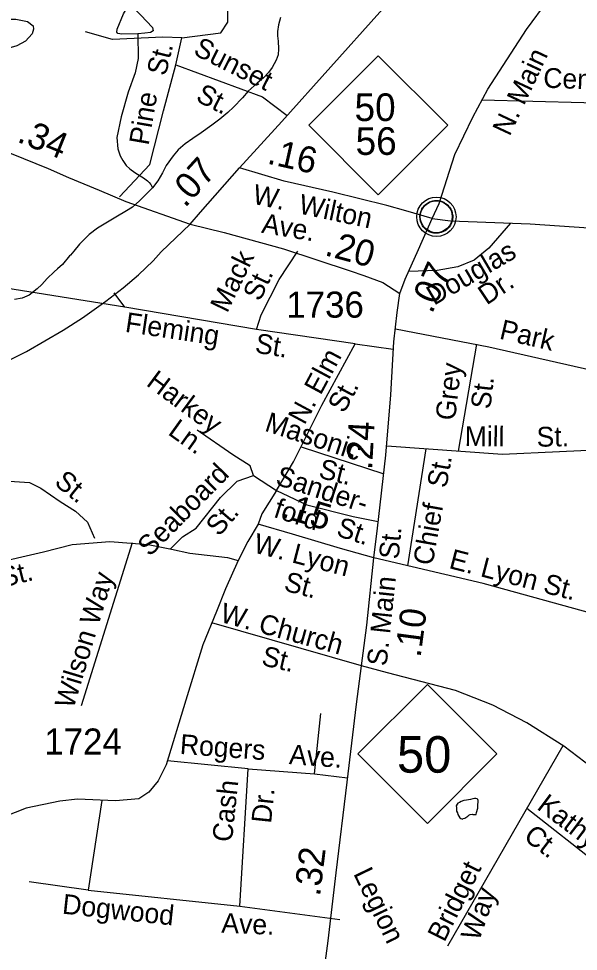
# Model space of a CAD drawing. Extents: x 2056842 to 2160602, y 826753 to 1016856.
# Drawn here: x 2090814 to 2093495, y 860118 to 864586 of the extents above; entities that cross this region are included whole.
import ezdxf

# ---------------------------------------------------------------- set-up
doc = ezdxf.new("R2010")
doc.units = 0
for name, color, linetype in [('Exist Civil Demographics Community CELL', 7, 'Continuous'), ('Exist Hydrographic Creek Single Shore', 7, 'Continuous'), ('Exist Hydrographic Misc Water Feature', 7, 'Continuous'), ('Exist Road Non-System Type 51', 7, 'Continuous'), ('Exist Road Non-System Type 51 Label', 7, 'Continuous'), ('Exist Road Primary NC Attributed', 7, 'Continuous'), ('Exist Road Primary NC Label', 7, 'Continuous'), ('Exist Road Primary NC Service Mileage Hundredths English Label', 7, 'Continuous'), ('Exist Road Primary NC Shield CELL', 7, 'Continuous'), ('Exist Road Primary NC Shield Number Label', 7, 'Continuous'), ('Exist Road Primary US Attributed', 7, 'Continuous'), ('Exist Road Primary US Mileage Hundredths English Label', 7, 'Continuous'), ('Exist Road Secondary Mileage Hundredths English Label', 7, 'Continuous'), ('Exist Road Secondary Type 51 Attributed', 7, 'Continuous'), ('Exist Road Secondary Type 51 Label', 7, 'Continuous'), ('Exist Road Secondary Type 51 Number Label', 7, 'Continuous')]:
    doc.layers.add(name, color=color, linetype=linetype)

msp = doc.modelspace()

# ---------------------------------------------------------------- linework, layer by layer
at = {"layer": 'Exist Civil Demographics Community CELL'}
msp.add_lwpolyline([(2092737.2, 863649.5), (2092738.1, 863655.1), (2092739.9, 863661.7), (2092742.8, 863668.9), (2092745.8, 863674.6), (2092749.1, 863680.3), (2092752.9, 863685.5), (2092756.8, 863689.8), (2092761.4, 863694.4), (2092766.9, 863699), (2092772.4, 863702.7), (2092777.3, 863705.5), (2092782.3, 863708), (2092787.8, 863710.3), (2092793.4, 863712.1), (2092797.7, 863713.3), (2092802.6, 863714), (2092806.7, 863714.7), (2092813.1, 863715), (2092817.5, 863714.9), (2092823.2, 863714.6), (2092828.1, 863713.9), (2092833, 863712.9), (2092838, 863711.5), (2092843.2, 863709.6), (2092849.8, 863706.6), (2092856.1, 863703.1), (2092861.1, 863699.6), (2092866.3, 863695.6), (2092869.6, 863692.5), (2092873.7, 863688.1), (2092877.6, 863683.4), (2092880.7, 863678.8), (2092883.8, 863673.8), (2092886.3, 863668.6), (2092888.3, 863663.6), (2092889.9, 863658.6), (2092891.1, 863654), (2092892.2, 863647.9), (2092892.9, 863643.2), (2092893.1, 863637.2), (2092892.9, 863631.5), (2092892.4, 863625.8), (2092891.4, 863620.3), (2092889.8, 863614.1), (2092887.9, 863608.3), (2092885.6, 863603.2), (2092882.4, 863597.2), (2092879.2, 863591.9), (2092875.7, 863587.2), (2092871.5, 863582.5), (2092866.2, 863577.5), (2092861.2, 863573.4), (2092856.2, 863569.9), (2092851.8, 863567.4), (2092845, 863564.2), (2092837.9, 863561.5), (2092831.9, 863560), (2092825.3, 863558.7), (2092820.9, 863558.2), (2092816.4, 863558), (2092810.8, 863558), (2092806.6, 863558.4), (2092800.9, 863559.1), (2092795, 863560.4), (2092790.4, 863561.7), (2092785.2, 863563.6), (2092780.6, 863565.6), (2092776.7, 863567.8), (2092769.9, 863571.9), (2092764.3, 863576.2), (2092759.4, 863580.7), (2092755, 863585.5), (2092751.8, 863589.5), (2092748.8, 863593.7), (2092744.7, 863600.8), (2092743, 863604.3), (2092741.3, 863608.3), (2092738.7, 863616.5), (2092737.2, 863623.6), (2092736.5, 863628.7), (2092736.1, 863635.1), (2092736.1, 863639.8), (2092736.6, 863646.2)], close=True, dxfattribs=at)
for centre, radius in [((2092814.8, 863637.1), 94.3), ((2092814.5, 863637.4), 76.7)]:
    msp.add_circle(centre, radius, dxfattribs=at)
at = {"layer": 'Exist Hydrographic Creek Single Shore'}
msp.add_lwpolyline([(2091454.6, 863775.1), (2091424.6, 863745.2), (2091392.8, 863713), (2091359, 863682.9), (2091330.9, 863664.8), (2091279, 863634.6), (2091223.3, 863602.4), (2091191.3, 863582.1), (2091151.1, 863552), (2091129.6, 863530.2), (2091105.2, 863506.3), (2091077.5, 863472), (2091061.7, 863454), (2091057.6, 863449.8), (2091023.7, 863407.9), (2090999.5, 863388), (2090984.2, 863373.7), (2090949.9, 863341.6), (2090923.9, 863313.5), (2090901.9, 863291.6), (2090864.2, 863261.2), (2090830.4, 863247.2), (2090794.3, 863241.4)], dxfattribs=at)
at = {"layer": 'Exist Hydrographic Misc Water Feature'}
for points in [[(2091385, 864514), (2091307.3, 864511.3), (2091288.9, 864515.3), (2091283.6, 864521.9), (2091284.9, 864535.1), (2091316.5, 864608.9), (2091331, 864632.6), (2091350.8, 864639.2), (2091367.9, 864633.9), (2091398.2, 864603.6), (2091454.9, 864543), (2091457.5, 864527.2), (2091445.7, 864519.2), (2091418, 864516.6), (2091385, 864514)], [(2090757.3, 864449.4), (2090711.2, 864466.5), (2090662.4, 864486.3), (2090644, 864499.5), (2090637.4, 864511.3), (2090644, 864527.2), (2090667.7, 864550.9), (2090708.5, 864574.6), (2090749.4, 864583.8), (2090800.7, 864583.8), (2090856.1, 864573.3), (2090883.7, 864552.2), (2090885.1, 864535.1), (2090878.5, 864514), (2090846.9, 864478.4), (2090804.7, 864456), (2090778.3, 864448.1), (2090757.3, 864449.4)], [(2092067.7, 864591), (2092058.2, 864556.8), (2092054.1, 864525), (2092054.3, 864503.1), (2092056.2, 864478.8), (2092058.4, 864441.1), (2092056.8, 864412.9), (2092046.5, 864386.9), (2092028.9, 864352.7), (2092010.9, 864328.7), (2091987.1, 864302.6), (2091956.7, 864276.8), (2091913.1, 864238.3), (2091885.2, 864206.5), (2091843.3, 864162.1), (2091815.7, 864136.2), (2091777.5, 864104.3), (2091739.8, 864075.9), (2091687.7, 864039.7), (2091647.9, 864011.6), (2091611.6, 863985.8), (2091578, 863957.2), (2091553.8, 863929.6), (2091520.2, 863883.2), (2091502.3, 863847.4), (2091480.4, 863809.4), (2091454.6, 863775.1)], [(2091385, 864514), (2091386.4, 864395.3), (2091371.9, 864326.8), (2091338.9, 864233.7), (2091304.7, 864115.1), (2091283.6, 864017.5), (2091288.3, 863962.7), (2091300.2, 863928.8), (2091312, 863906.7), (2091328, 863882.7), (2091346.3, 863867), (2091370.5, 863848.7), (2091396.3, 863833.1), (2091412.5, 863822.9), (2091430.6, 863809.2), (2091438.6, 863801.1), (2091446.8, 863791.3), (2091450.3, 863785.1), (2091454.6, 863775.1)], [(2093005.6, 860774.3), (2093007.6, 860784.1), (2093013.6, 860804.3), (2093013.4, 860820.2), (2093015.2, 860834.6), (2093015.4, 860840.2), (2093013.4, 860846.2), (2093009.5, 860848.4), (2093003.3, 860850.2), (2092997.4, 860850.3), (2092989.6, 860848.2), (2092977.7, 860846.4), (2092959.6, 860842.2), (2092945.7, 860840.2), (2092933.4, 860836), (2092925.2, 860832), (2092917.2, 860827.9), (2092913.7, 860824), (2092909.8, 860816), (2092911.5, 860808.1), (2092911.3, 860789.9), (2092915.6, 860781.9), (2092917.6, 860773.9), (2092921.9, 860765.9), (2092927.7, 860758.1), (2092931.8, 860754.3), (2092940, 860751.8), (2092943.6, 860754.1), (2092951.6, 860756.2), (2092965.6, 860766.2), (2092969.7, 860770.1), (2092977.5, 860774.1), (2092985.5, 860776.1), (2092989.6, 860774.3), (2092997.6, 860774.3), (2093005.6, 860774.3)]]:
    msp.add_lwpolyline(points, dxfattribs=at)
at = {"layer": 'Exist Road Non-System Type 51'}
for p, q in [((2091566, 864365), (2091595.1, 864493.9)), ((2091322.2, 863203.5), (2090553.7, 863326.2)), ((2092425.9, 863027.8), (2091953.4, 863097.5)), ((2092425.9, 863027.8), (2092608.1, 863002.6)), ((2093006.6, 863026.3), (2092919.8, 862513.9)), ((2092764.8, 862525.2), (2092676.7, 861965.6)), ((2091938.8, 862397), (2092048.9, 862326.4)), ((2091356.9, 862074.5), (2091113, 861294.7)), ((2092455.8, 861485.8), (2091739.1, 861691.4)), ((2092230.5, 860968.6), (2092261.7, 861257.5)), ((2093421.1, 861103.4), (2092867.8, 860143.1)), ((2091913.8, 860992.5), (2091526.4, 861030.4)), ((2091873.3, 860334.7), (2091913.8, 860992.5)), ((2091913.8, 860992.5), (2092230.5, 860968.6)), ((2092230.5, 860968.6), (2092389.6, 860950)), ((2091212.3, 860841.6), (2091146.3, 860411.6)), ((2093248.4, 860803.6), (2093635.8, 860499)), ((2091146.3, 860411.6), (2090863.9, 860451.1)), ((2091146.3, 860411.6), (2091873.3, 860334.7)), ((2091873.3, 860334.7), (2092352, 860271.3))]:
    msp.add_line(p, q, dxfattribs=at)
for points in [[(2091595.1, 864493.9), (2091782, 864518.8), (2091815.2, 864568.7), (2091815.2, 865017.7), (2091835, 865130.9)], [(2091595.1, 864493.9), (2091503.7, 864498), (2091262.8, 864485.6), (2091134, 864523)], [(2091296.5, 863732.8), (2091441.4, 863887), (2091507.8, 864144.7), (2091566, 864365)], [(2091566, 864365), (2091981.4, 864211.2), (2092099.7, 864121.6)], [(2094253.6, 864164.4), (2093032.2, 864194.9)], [(2093170.6, 863606.8), (2093065.6, 863487.2), (2092995.8, 863429), (2092917.3, 863397), (2092818.4, 863379.5), (2092681.5, 863375.1)], [(2091953.4, 863097.5), (2091976.2, 863168.1), (2092061.4, 863336.5), (2092150.7, 863471.6)], [(2091953.4, 863097.5), (2091322.2, 863203.5), (2091270.9, 863273.1)], [(2092618.3, 863100.9), (2093066.5, 863014.8), (2093763.4, 862855.8)], [(2092048.9, 862326.4), (2092131, 862462.5), (2092266, 862734.8), (2092425.9, 863027.8)], [(2090399.7, 862808.1), (2090519.6, 862692), (2090550.2, 862633.8), (2090590, 862566.5), (2090623.6, 862483.8), (2090632.8, 862444), (2090672.6, 862391.9), (2090770.5, 862370.5), (2090865.4, 862364.4), (2090920.5, 862336.8), (2091012.3, 862272.5), (2091085.7, 862226.6), (2091143.8, 862174.5), (2091177.5, 862098)], [(2091938.8, 862397), (2091922.2, 862444.8), (2091839.1, 862496.8), (2091668.8, 862615.3)], [(2092166.6, 862534.5), (2092562.5, 862405.2)], [(2093677.2, 862524.3), (2093131.9, 862498.3), (2092578, 862538.9)], [(2091541.3, 862045.8), (2091598.2, 862104), (2091664.7, 862145.5), (2091781, 862293.1), (2091859.9, 862370), (2091938.8, 862397)], [(2092048.9, 862326.4), (2091978.3, 862214.1), (2091961.3, 862164.7)], [(2092048.9, 862326.4), (2092194.3, 862257.8), (2092416.5, 862201.7), (2092536.2, 862178)], [(2093658.5, 861709.6), (2093039.5, 861880), (2092515.8, 862003.6)]]:
    msp.add_lwpolyline(points, dxfattribs=at)
at = {"layer": 'Exist Road Primary NC Attributed'}
for points in [[(2089971.1, 864267.7), (2090178.7, 864181.5), (2090355.3, 864111.6), (2090954.8, 863867.6), (2091051.6, 863825.7), (2091199.3, 863764.1), (2091326.3, 863710.4), (2091634.7, 863602.4)], [(2092668.5, 863665.4), (2092577.6, 863691.7), (2092319, 863755.1), (2092085.9, 863807.6), (2091871.9, 863872)], [(2092795.1, 863628.8), (2092668.5, 863665.4)], [(2092639.9, 863268.8), (2092664.8, 863338.4), (2092729.2, 863479.7), (2092795.1, 863628.8)], [(2092795.1, 863628.8), (2092882.4, 863617.4), (2093264, 863603.4), (2094716.8, 863504.7), (2095267.2, 863471.4), (2095984.7, 863422.6), (2096537.2, 863385.2), (2096819.9, 863367.2)], [(2092515.8, 862003.6), (2092532.4, 862144.9), (2092572.9, 862495.1), (2092596.5, 862783.8), (2092611.3, 863038.6), (2092626.9, 863177.8), (2092639.9, 863268.8)], [(2092455.8, 861485.8), (2092481.5, 861680.4), (2092515.8, 862003.6)], [(2092249.2, 859809.6), (2092296.7, 860169.4), (2092334.1, 860493.7), (2092387, 860929.1), (2092432.7, 861303.2), (2092455.8, 861485.8)]]:
    msp.add_lwpolyline(points, dxfattribs=at)
at = {"layer": 'Exist Road Primary NC Shield CELL'}
for points in [[(2092203.1, 864075.2), (2092536.1, 864408.2), (2092869.1, 864075.2), (2092536.1, 863742.2)], [(2092439.2, 861064), (2092772.2, 861397), (2093105.2, 861064), (2092772.2, 860731)]]:
    msp.add_lwpolyline(points, close=True, dxfattribs=at)
at = {"layer": 'Exist Road Primary US Attributed'}
for points in [[(2091871.9, 863872), (2092073.9, 864092.9), (2092544.4, 864617.6), (2092704.3, 864777.7), (2092921.1, 864973.9), (2093332.5, 865342), (2093594.2, 865568.5), (2093818.5, 865763.9), (2093953.5, 865905.2), (2094073.2, 866070.1)], [(2091634.7, 863602.4), (2091685, 863659.5), (2091871.9, 863872)], [(2088403.2, 861886.8), (2088556.2, 862014), (2088768, 862133), (2088966.7, 862232.6), (2089068, 862279), (2089371.2, 862399.3), (2089582.8, 862480.5), (2090175.9, 862708.8), (2090521.1, 862842), (2090693.5, 862914.1), (2090851.8, 862991.4), (2091027, 863093.2), (2091119.9, 863153.1), (2091231.2, 863233.6), (2091314, 863297.4), (2091387.9, 863359.5), (2091458.4, 863425.6), (2091497.1, 863468.8), (2091634.7, 863602.4)]]:
    msp.add_lwpolyline(points, dxfattribs=at)
at = {"layer": 'Exist Road Secondary Type 51 Attributed'}
for points in [[(2092795.1, 863628.8), (2092828.4, 863700.5), (2092903.7, 863934.9), (2092988.8, 864114.7), (2093061, 864248.2), (2093246.7, 864534.1), (2093454.6, 864816.6), (2093784.8, 865194.9), (2094030.9, 865495.2)], [(2091634.7, 863602.4), (2091797.7, 863561.8), (2092082.2, 863482.8), (2092402.1, 863378.9), (2092467.7, 863355.3)], [(2092467.7, 863355.3), (2092557.8, 863322.8), (2092639.9, 863268.8)], [(2092515.8, 862003.6), (2092354.8, 862048.3), (2092125.3, 862116.9), (2091961.3, 862164.7), (2091910.9, 862081), (2091865.2, 861990.6)], [(2088403.2, 861886.8), (2088523.5, 861870), (2088674, 861846.5), (2088978.8, 861812.4), (2089435.2, 861745.4), (2089618, 861748.5), (2089758.2, 861762), (2090218.7, 861866.4), (2090441, 861918.4), (2090932.7, 862032.2), (2091069.7, 862066.5), (2091250.4, 862081), (2091434.8, 862068), (2091545.7, 862044.9)], [(2091545.7, 862044.9), (2091634.2, 862026.5), (2091813.8, 862004.6), (2091865.2, 861990.6)], [(2091865.2, 861990.6), (2091804.5, 861855), (2091761.9, 861745.9), (2091695.4, 861586.9), (2091613.9, 861321.4), (2091521, 861012.2), (2091482.5, 860935.3), (2091436.8, 860880.2), (2091389.1, 860849.1), (2091276.9, 860838.7), (2091095.2, 860847), (2091010.6, 860837.1), (2090849.6, 860803.9), (2090682.4, 860739.4), (2090581.7, 860685.4), (2090449.3, 860579.9), (2090333, 860439.6), (2090231.2, 860298.3), (2090068.7, 860070.2)], [(2096292.4, 858449.9), (2096015.1, 858656.7), (2095761, 858892.7), (2095692.5, 858988.3), (2095649.6, 859080.7), (2095484.5, 859551.4), (2095411.8, 859807), (2095360.9, 859914.1), (2095309, 859982.7), (2095232.1, 860045), (2095049.4, 860146.8), (2094696.3, 860342.2), (2094155.3, 860601), (2093820.9, 860794.2), (2093645.4, 860909.6), (2093560.2, 860999), (2093425.2, 861100.8), (2093248.7, 861213), (2093084.6, 861298.2), (2092907, 861367.9), (2092581, 861453.1), (2092455.8, 861485.8)]]:
    msp.add_lwpolyline(points, dxfattribs=at)

# ---------------------------------------------------------------- texts
at = {"layer": 'Exist Road Non-System Type 51 Label'}
for s, rotation, p in [('Sunset', 333.2091, (2091645.5, 864417)), ('St.', 76.319, (2091518.1, 864308.2)), ('Cemetery', 357.8831, (2093325.7, 864255.8)), ('St.', 333.2091, (2091657.4, 864194.3)), ('Pine', 80.1889, (2091435.7, 863976.1)), ('Douglas', 30.4193, (2092803.8, 863210.5)), ('Mack', 64.2922, (2091812.6, 863172.5)), ('St.', 64.2922, (2091969.3, 863227.7)), ('Dr.', 33.963, (2093055.6, 863211.6)), ('Fleming', 351.5147, (2091320.2, 863086.5)), ('Park', 346.8941, (2093112.7, 863053.8)), ('St.', 350.6954, (2091942.1, 862986.8)), ('N. Elm', 61.7207, (2092183.3, 862636.1)), ('Grey', 83.5086, (2092904.3, 862658.4)), ('Harkey', 323.3697, (2091420.2, 862832.3)), (' St.', 61.7207, (2092356.2, 862660.8)), ('St.', 83.5086, (2093073.6, 862713.1)), ('Masonic', 342.0558, (2091987.4, 862613)), ('Ln.', 324.4094, (2091524.2, 862597.3)), ('Mill', 359.3528, (2092950.2, 862539.1)), ('St.', 1.0343, (2093295.8, 862535.3)), ('Seaboard', 45.4498, (2091441.5, 862005.6)), ('St.', 346.2559, (2092246.1, 862387.7)), ('St.', 79.8685, (2092862.8, 862334.2)), ('St.', 320.9862, (2090979.5, 862357.2)), ('Sander-', 342.1079, (2092039.3, 862356)), ('ford', 342.1079, (2092030, 862200.1)), ('St.', 49.3973, (2091773.9, 862101.6)), ('Chief', 79.8685, (2092795.9, 861963.1)), ('St.', 342.1079, (2092330.7, 862110.5)), ('W. Lyon', 345.4456, (2091933.2, 862030.5)), ('E. Lyon St.', 345.4456, (2092870.9, 861955)), ('Wilson Way', 73.2877, (2091075.7, 861276.2)), (' St.', 345.4456, (2092045.6, 861856.1)), ('W. Church', 344.6698, (2091773.6, 861697.8)), ('St.', 346.9316, (2091972.4, 861490.4)), ('Rogers', 355.8118, (2091583.8, 861064.3)), ('Ave.', 355.8118, (2092106.9, 861015.6)), ('Cash', 83.9925, (2091835.3, 860639.1)), ('Dr.', 83.9925, (2092022.7, 860728.5)), ('Kathy', 322.9076, (2093291.7, 860803.1)), ('Ct.', 322.9076, (2093227.5, 860657.4)), ('Bridget', 63.4512, (2092853, 860158.5)), ('Legion', 295.7163, (2092415.3, 860491.3)), ('Way', 70.6312, (2093018.8, 860163)), ('Dogwood', 353.8816, (2091019.3, 860299.5)), ('Ave.', 357.7237, (2091783.5, 860207.5))]:
    msp.add_text(s, height=95, rotation=rotation, dxfattribs=at).set_placement(p)
at = {"layer": 'Exist Road Primary NC Label'}
for s, rotation, p in [('W.  Wilton', 348.016, (2091929.5, 863701)), ('Ave.', 350.4571, (2091973.6, 863561.2)), ('St.', 84.9574, (2092634.3, 861994.3)), ('S. Main', 83.9726, (2092576.2, 861482.2))]:
    msp.add_text(s, height=95, rotation=rotation, dxfattribs=at).set_placement(p)
at = {"layer": 'Exist Road Primary NC Service Mileage Hundredths English Label'}
for s, rotation, p in [('.34', 337.945, (2090801.2, 863998.3)), ('.16', 347.3141, (2091999.8, 863892.7)), ('.07', 65.5077, (2092793.5, 863168.6)), ('.24', 86.8443, (2092506.3, 862422.3)), ('.10', 82.4784, (2092738.8, 861523)), ('.32', 83.065, (2092257.1, 860379))]:
    msp.add_text(s, height=125, rotation=rotation, dxfattribs=at).set_placement(p)
at = {"layer": 'Exist Road Primary NC Shield Number Label'}
for s, height, p in [('50', 132.5, (2092422.7, 864095.7)), ('56', 132.5, (2092427.7, 863933.5)), ('50', 175, (2092626.3, 860974.2))]:
    msp.add_text(s, height=height, dxfattribs=at).set_placement(p)
at = {"layer": 'Exist Road Primary US Mileage Hundredths English Label'}
msp.add_text('.07', height=125, rotation=47.7432, dxfattribs=at).set_placement((2091610.4, 863677))
at = {"layer": 'Exist Road Secondary Mileage Hundredths English Label'}
for s, rotation, p in [('.20', 344.7598, (2092275.1, 863454.2)), ('.15', 343.3615, (2092066.1, 862199.8))]:
    msp.add_text(s, height=125, rotation=rotation, dxfattribs=at).set_placement(p)
at = {"layer": 'Exist Road Secondary Type 51 Label'}
for s, rotation, p in [('N. Main', 64.8356, (2093165.5, 864019.2)), ('St.', 13.5745, (2090738.6, 861861.4))]:
    msp.add_text(s, height=95, rotation=rotation, dxfattribs=at).set_placement(p)
at = {"layer": 'Exist Road Secondary Type 51 Number Label'}
for s, p in [('1736', (2092095.5, 863153.8)), ('1724', (2090936.1, 861060.9))]:
    msp.add_text(s, height=125, dxfattribs=at).set_placement(p)

doc.saveas('drawing.dxf')
